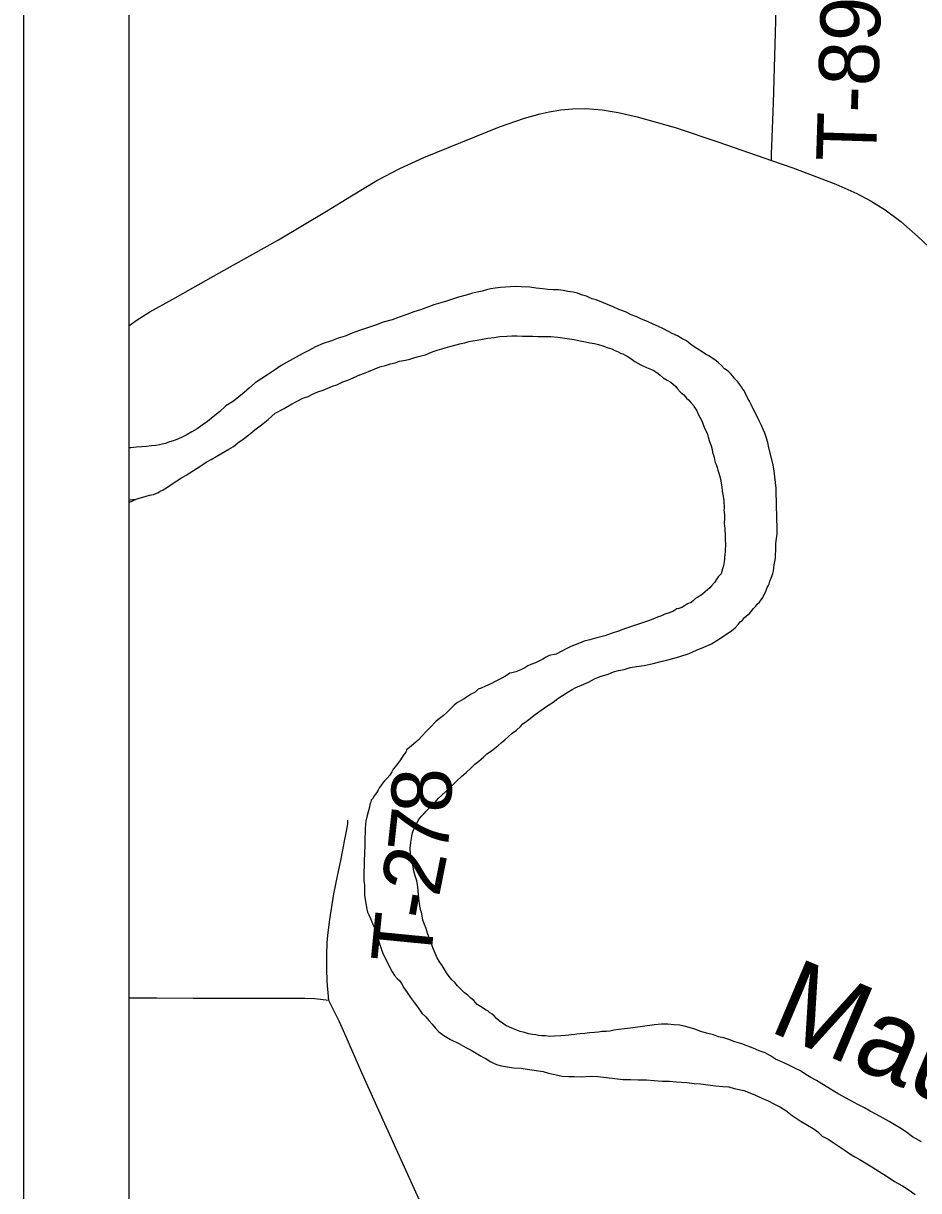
# Model space of a CAD drawing. Extents: x 0 to 64.8, y -5 to 22.
# Drawn here: x 2 to 2.849, y 18.186 to 19.293 of the extents above; entities that cross this region are included whole.
import ezdxf

# ---------------------------------------------------------------- set-up
doc = ezdxf.new("R2010")
doc.units = 0
for name, color, linetype in [('GM_X_Adjacent_County', 7, 'Continuous'), ('GM_X_County', 7, 'Continuous'), ('GM_X_Major_River', 7, 'Continuous'), ('GM_X_Major_River_Text', 7, 'Continuous'), ('GM_X_Minor_River', 7, 'Continuous'), ('GM_X_Township', 7, 'Continuous'), ('GM_X_Township_Road', 7, 'Continuous'), ('GM_X_Township_Road_Text', 7, 'Continuous'), ('SH_Data', 7, 'Continuous')]:
    doc.layers.add(name, color=color, linetype=linetype)

msp = doc.modelspace()

# ---------------------------------------------------------------- linework, layer by layer
at = {"layer": 'GM_X_Adjacent_County'}
msp.add_lwpolyline([(2.1, 19.9176), (2.1, 14.1), (8.9, 14.1), (8.9, 19.781)], dxfattribs=at)
at = {"layer": 'GM_X_County'}
msp.add_lwpolyline([(2.1, 19.9176), (2.1, 14.1), (8.9, 14.1), (8.9, 19.781)], dxfattribs=at)
at = {"layer": 'GM_X_Major_River'}
for points in [[(2.7137, 18.7927), (2.7137, 18.7957), (2.7138, 18.7999), (2.7143, 18.8044), (2.7148, 18.8086), (2.7149, 18.812), (2.715, 18.8162), (2.7147, 18.8223), (2.7145, 18.8272), (2.7142, 18.8337), (2.7144, 18.8402), (2.7141, 18.8463), (2.7139, 18.8523), (2.7132, 18.8577), (2.7126, 18.863), (2.712, 18.8687), (2.711, 18.8741), (2.7103, 18.8783), (2.7071, 18.8905), (2.7061, 18.8955), (2.7047, 18.8997), (2.7033, 18.9043), (2.7018, 18.9078), (2.7, 18.9116), (2.6982, 18.9154), (2.6967, 18.9189), (2.6949, 18.922), (2.6934, 18.9254), (2.6916, 18.9289), (2.6902, 18.9316), (2.6887, 18.9347), (2.6872, 18.9374), (2.6858, 18.9401), (2.6847, 18.9424), (2.684, 18.9443), (2.6825, 18.9462), (2.681, 18.9485), (2.6792, 18.9509), (2.6777, 18.9532), (2.6747, 18.9559), (2.6729, 18.9586), (2.6706, 18.9609), (2.6684, 18.9633), (2.665, 18.9656), (2.662, 18.9687), (2.6594, 18.9711), (2.6568, 18.9734), (2.6542, 18.975), (2.6508, 18.9774), (2.647, 18.9793), (2.6429, 18.9821), (2.6373, 18.9856), (2.6328, 18.9888), (2.629, 18.9919), (2.6245, 18.9943), (2.6204, 18.9967), (2.6155, 18.9991), (2.6106, 19.0015), (2.6064, 19.0038), (2.6023, 19.0058), (2.5974, 19.0079), (2.5921, 19.0103), (2.5864, 19.0127), (2.5819, 19.0147), (2.5766, 19.0167), (2.571, 19.0195), (2.5649, 19.0219), (2.5593, 19.0243), (2.5434, 19.0308), (2.5396, 19.032), (2.5366, 19.0332), (2.534, 19.0344), (2.5294, 19.0356), (2.5257, 19.0372), (2.5215, 19.0381), (2.5165, 19.039), (2.512, 19.0398), (2.5074, 19.0403), (2.5025, 19.0404), (2.4975, 19.0409), (2.4926, 19.0414), (2.4865, 19.0419), (2.4804, 19.0428), (2.4721, 19.0434), (2.4667, 19.0435), (2.4621, 19.0433), (2.4572, 19.043), (2.4526, 19.0427), (2.4476, 19.0421), (2.4434, 19.0414), (2.4392, 19.0404), (2.435, 19.0393), (2.4304, 19.0383), (2.425, 19.0369), (2.4201, 19.0355), (2.4128, 19.0334), (2.407, 19.0316), (2.4013, 19.0298), (2.3959, 19.028), (2.3894, 19.0263), (2.3828, 19.0238)], [(2.3828, 19.0238), (2.3767, 19.0216), (2.3702, 19.0195), (2.3636, 19.017), (2.3563, 19.0145), (2.3498, 19.012), (2.3414, 19.0099), (2.3341, 19.007), (2.3264, 19.0045), (2.3187, 19.0017), (2.3118, 18.9992), (2.3052, 18.9966), (2.2987, 18.9945), (2.2922, 18.992), (2.2845, 18.9895), (2.2772, 18.9863), (2.2706, 18.983), (2.2645, 18.9797), (2.2444, 18.9688), (2.2382, 18.9643), (2.2324, 18.9603), (2.2262, 18.9562), (2.22, 18.9522), (2.2146, 18.9474), (2.2095, 18.9429), (2.2045, 18.9389), (2.1994, 18.9348), (2.1921, 18.9304), (2.1859, 18.9248), (2.18, 18.92), (2.1746, 18.9156), (2.1696, 18.9119), (2.1649, 18.9086), (2.1599, 18.9057), (2.1545, 18.9027), (2.1499, 18.9002), (2.1456, 18.8984), (2.1422, 18.8973), (2.1387, 18.8963), (2.1349, 18.8948), (2.1318, 18.8941), (2.1291, 18.8934), (2.1257, 18.8928), (2.1215, 18.8925), (2.1169, 18.8918), (2.1123, 18.8915), (2.1074, 18.8913), (2.102, 18.8906), (2.1, 18.8905)], [(2.1, 18.8414), (2.102, 18.8412), (2.1039, 18.8415), (2.107, 18.8419), (2.1089, 18.8426), (2.112, 18.8433), (2.1154, 18.8443), (2.1197, 18.8457), (2.1235, 18.8464), (2.1258, 18.8471), (2.1277, 18.8478), (2.1296, 18.8493), (2.1327, 18.8508), (2.1366, 18.8533), (2.1412, 18.8563), (2.1455, 18.8592), (2.1501, 18.8622), (2.1544, 18.8647), (2.1683, 18.8735), (2.1733, 18.8768), (2.178, 18.8794), (2.1834, 18.8827), (2.1872, 18.8849), (2.1911, 18.8871), (2.195, 18.8893), (2.1992, 18.8918), (2.2035, 18.8952), (2.2085, 18.8989), (2.2139, 18.9029), (2.2194, 18.9077), (2.226, 18.9125), (2.2322, 18.9173), (2.2388, 18.9233), (2.2473, 18.928), (2.2538, 18.9317), (2.2596, 18.9349), (2.265, 18.9375), (2.27, 18.9393), (2.2743, 18.9415), (2.2793, 18.9436), (2.2843, 18.9454), (2.2889, 18.9472), (2.2931, 18.949), (2.2973, 18.9504), (2.3031, 18.953), (2.3077, 18.9548), (2.3127, 18.9569), (2.3177, 18.9591), (2.3227, 18.9609), (2.3273, 18.9631), (2.3327, 18.9652), (2.3381, 18.9674), (2.3435, 18.9688), (2.3481, 18.9702), (2.3527, 18.9712), (2.3569, 18.9727), (2.3623, 18.9737), (2.3665, 18.9747), (2.3703, 18.9758), (2.3734, 18.9768), (2.3772, 18.9779), (2.3814, 18.9789), (2.3849, 18.9804), (2.3887, 18.9818), (2.3926, 18.9832), (2.3968, 18.9843), (2.3999, 18.9854), (2.4045, 18.9868), (2.4152, 18.9896), (2.4186, 18.9903), (2.4225, 18.9913), (2.4263, 18.992), (2.4305, 18.9926), (2.4355, 18.9937), (2.4405, 18.9947), (2.4466, 18.9953), (2.4519, 18.996), (2.4584, 18.9966), (2.4634, 18.9968), (2.4683, 18.9967), (2.4733, 18.9966), (2.4779, 18.9965), (2.4832, 18.9964), (2.4881, 18.9963), (2.4939, 18.9961), (2.5003, 18.996), (2.5068, 18.9955), (2.5136, 18.9946)], [(2.5136, 18.9946), (2.5224, 18.9932), (2.5281, 18.9919), (2.533, 18.9911), (2.5372, 18.9902), (2.5417, 18.9894), (2.5455, 18.9885), (2.5497, 18.9873), (2.5538, 18.9857), (2.558, 18.9844), (2.561, 18.9828), (2.564, 18.9816), (2.5663, 18.9804), (2.5685, 18.9796), (2.5708, 18.9784), (2.5727, 18.9776), (2.5761, 18.9753), (2.5798, 18.9725), (2.5855, 18.9693), (2.5911, 18.9669), (2.5957, 18.9649), (2.599, 18.9633), (2.602, 18.961), (2.6039, 18.9594), (2.6069, 18.9571), (2.6107, 18.9547), (2.614, 18.9527), (2.6189, 18.9488), (2.6204, 18.9465), (2.6234, 18.9434), (2.6263, 18.9407), (2.6289, 18.9376), (2.6308, 18.936), (2.6327, 18.934), (2.6356, 18.9306), (2.6367, 18.9286), (2.6386, 18.9255), (2.64, 18.9225), (2.6419, 18.919), (2.6437, 18.9155), (2.6451, 18.9117), (2.6466, 18.9079), (2.6484, 18.9044), (2.6494, 18.9006), (2.6509, 18.8964), (2.6523, 18.8925), (2.6534, 18.8891), (2.6537, 18.886), (2.6544, 18.8837), (2.6551, 18.8818), (2.6554, 18.8792), (2.6561, 18.8765), (2.6572, 18.8746), (2.6579, 18.8719), (2.6586, 18.8692), (2.6597, 18.8665), (2.6604, 18.8635), (2.6611, 18.8604), (2.6618, 18.8573), (2.6625, 18.8531), (2.6628, 18.8493), (2.6635, 18.8467), (2.6638, 18.8444), (2.6641, 18.8425), (2.6645, 18.8402), (2.6644, 18.8379), (2.6647, 18.8356), (2.6647, 18.8333), (2.6643, 18.8314), (2.6646, 18.8295), (2.6649, 18.8268), (2.6649, 18.8246), (2.6647, 18.8185), (2.6651, 18.8166), (2.6654, 18.8139), (2.6653, 18.8116), (2.6657, 18.8093), (2.6656, 18.8074), (2.6656, 18.8048), (2.6655, 18.8029), (2.6658, 18.7998), (2.6658, 18.7976), (2.6657, 18.7945), (2.6656, 18.7919), (2.6652, 18.7892), (2.6651, 18.7865), (2.6651, 18.7846), (2.6647, 18.7828), (2.6642, 18.7801), (2.6638, 18.7778), (2.663, 18.7756), (2.6617, 18.771), (2.659, 18.7681), (2.6578, 18.7662), (2.6555, 18.7628), (2.6527, 18.7595), (2.6511, 18.7576), (2.6488, 18.7557), (2.6465, 18.7539), (2.6442, 18.7517), (2.6414, 18.7498)], [(2.3675, 18.5162), (2.368, 18.5199), (2.3684, 18.5226), (2.3692, 18.5252), (2.37, 18.5283), (2.3716, 18.5313), (2.3732, 18.5343), (2.3748, 18.5377), (2.3764, 18.5395), (2.378, 18.5414), (2.3799, 18.5432), (2.3819, 18.5459), (2.3842, 18.5481), (2.3866, 18.5503), (2.3885, 18.5526), (2.3905, 18.5544), (2.3936, 18.5581), (2.3967, 18.5607), (2.4006, 18.5644), (2.4111, 18.5745), (2.4154, 18.5789), (2.4201, 18.5826), (2.4243, 18.5867), (2.4282, 18.5904), (2.4321, 18.5934), (2.4364, 18.5971), (2.4395, 18.6004), (2.443, 18.6026), (2.4469, 18.6052), (2.4504, 18.6082), (2.4531, 18.6108), (2.4566, 18.6134), (2.4601, 18.6167), (2.4636, 18.6197), (2.4678, 18.6226), (2.4714, 18.6263), (2.4737, 18.6286), (2.4768, 18.6308), (2.4807, 18.6337), (2.4842, 18.6367), (2.4888, 18.64), (2.4966, 18.6455), (2.5024, 18.6492), (2.507, 18.6529), (2.5113, 18.6555), (2.5159, 18.6584), (2.5205, 18.6613), (2.524, 18.6631), (2.5294, 18.6653), (2.5359, 18.6682), (2.5417, 18.6715), (2.5471, 18.6736), (2.5548, 18.6758), (2.5598, 18.6779), (2.5644, 18.6793), (2.5698, 18.6804), (2.5755, 18.6821), (2.5816, 18.6831), (2.5889, 18.6841), (2.5973, 18.6858), (2.6046, 18.6879), (2.6111, 18.6893), (2.6172, 18.6911), (2.6226, 18.6925), (2.6314, 18.6953), (2.6384, 18.6986), (2.6453, 18.7014), (2.6526, 18.7047), (2.6588, 18.7084), (2.6716, 18.7168), (2.6751, 18.7198), (2.6778, 18.7228), (2.6798, 18.7254), (2.6821, 18.7272), (2.684, 18.7295), (2.686, 18.7313), (2.6883, 18.7332), (2.6903, 18.7354), (2.6926, 18.738), (2.6946, 18.7402), (2.6961, 18.7421), (2.6981, 18.744), (2.6997, 18.7462), (2.7012, 18.7485), (2.7024, 18.7507), (2.704, 18.7537), (2.7048, 18.756), (2.7056, 18.7579), (2.7065, 18.7597), (2.7073, 18.7616), (2.7081, 18.7639), (2.7089, 18.7662), (2.7101, 18.7695), (2.7109, 18.7714), (2.7113, 18.7737), (2.7118, 18.7764), (2.7122, 18.7794), (2.7127, 18.7828), (2.7132, 18.7862), (2.7132, 18.7896), (2.7137, 18.7927)], [(2.6414, 18.7498), (2.6395, 18.7487), (2.6376, 18.7476), (2.6356, 18.7458), (2.6333, 18.7439), (2.6298, 18.7425), (2.6271, 18.7406), (2.6244, 18.7392), (2.6217, 18.7381), (2.6198, 18.7378), (2.616, 18.7352), (2.6114, 18.7338), (2.6083, 18.7327), (2.6052, 18.7313), (2.6014, 18.7298), (2.5971, 18.728), (2.5921, 18.7262), (2.5864, 18.7241), (2.5749, 18.7205), (2.571, 18.7191), (2.5645, 18.7166), (2.5583, 18.7148), (2.5514, 18.7123), (2.5438, 18.7102), (2.5372, 18.7085), (2.5319, 18.7071), (2.5276, 18.7053), (2.5234, 18.7038), (2.5192, 18.702), (2.5149, 18.6999), (2.5107, 18.6977), (2.5053, 18.6948), (2.4988, 18.6934), (2.4957, 18.6919), (2.4926, 18.6901), (2.4895, 18.6886), (2.4857, 18.6865), (2.4814, 18.685), (2.4784, 18.6836), (2.4757, 18.6817), (2.4718, 18.6799), (2.4672, 18.6781), (2.4634, 18.6771), (2.4614, 18.6767), (2.4572, 18.6738), (2.4533, 18.6716), (2.4487, 18.6694), (2.4433, 18.6665), (2.4383, 18.6643), (2.4341, 18.6625), (2.4314, 18.6615), (2.4286, 18.6589), (2.4248, 18.6567), (2.4213, 18.6545), (2.4182, 18.6523), (2.4147, 18.6504), (2.4124, 18.6493), (2.4105, 18.6479), (2.4086, 18.6464), (2.4043, 18.6419), (2.4012, 18.6393), (2.3984, 18.6367), (2.3945, 18.6334), (2.3914, 18.6312), (2.3856, 18.6249), (2.3817, 18.6212), (2.3782, 18.6174), (2.3743, 18.6133), (2.37, 18.6093), (2.3661, 18.6063), (2.3638, 18.6044), (2.3626, 18.6018), (2.3602, 18.5988), (2.3578, 18.5947), (2.3551, 18.591), (2.3527, 18.588), (2.3508, 18.5857), (2.3496, 18.5831), (2.3476, 18.5801), (2.3449, 18.5771), (2.3425, 18.5745), (2.3409, 18.5727), (2.3398, 18.5708), (2.3378, 18.5682), (2.3366, 18.5659), (2.335, 18.5633), (2.3331, 18.5607), (2.3315, 18.558), (2.3299, 18.5562), (2.3295, 18.5543), (2.3287, 18.5524), (2.3282, 18.5497), (2.3274, 18.5463), (2.3262, 18.5418), (2.3249, 18.5365), (2.3244, 18.5331), (2.3243, 18.5293), (2.3242, 18.5251), (2.3238, 18.521), (2.324, 18.5164), (2.3239, 18.5118)], [(2.7322, 18.3018), (2.7266, 18.3046), (2.7206, 18.3074), (2.7134, 18.3106), (2.7085, 18.3137), (2.7036, 18.3165), (2.698, 18.3185), (2.6923, 18.3209), (2.687, 18.3229), (2.6813, 18.325), (2.6749, 18.327), (2.6692, 18.3291), (2.6643, 18.3307), (2.6594, 18.3319), (2.6545, 18.3336), (2.648, 18.3352), (2.6424, 18.3369), (2.6367, 18.3389), (2.6314, 18.3406), (2.6268, 18.3418), (2.6227, 18.3427), (2.6173, 18.3432), (2.6113, 18.3437), (2.6052, 18.3438), (2.5987, 18.3432), (2.5757, 18.3399), (2.57, 18.3393), (2.5647, 18.3387), (2.5601, 18.338), (2.5562, 18.3373), (2.5528, 18.337), (2.549, 18.3367), (2.5455, 18.3361), (2.5417, 18.3358), (2.5371, 18.3355), (2.5326, 18.3348), (2.528, 18.3346), (2.5249, 18.3342), (2.523, 18.3339), (2.5196, 18.3336), (2.5173, 18.3333), (2.5142, 18.333), (2.5096, 18.3327), (2.5039, 18.3324), (2.4993, 18.3322), (2.4952, 18.3326), (2.4917, 18.3327), (2.4887, 18.3332), (2.486, 18.3336), (2.483, 18.3341), (2.4792, 18.3345), (2.4754, 18.3358), (2.4713, 18.337), (2.4679, 18.3382), (2.4648, 18.3394), (2.4611, 18.341), (2.4577, 18.3426), (2.4543, 18.3446), (2.4513, 18.347), (2.4487, 18.3493), (2.4464, 18.3516), (2.4446, 18.3532), (2.4423, 18.3544), (2.4404, 18.3563), (2.4382, 18.3575), (2.4352, 18.3595), (2.4303, 18.3626), (2.4273, 18.3661), (2.4243, 18.3685), (2.4214, 18.3712), (2.4184, 18.3736), (2.4116, 18.3802), (2.4091, 18.3833), (2.4064, 18.386), (2.4038, 18.3891), (2.4013, 18.3926), (2.3991, 18.3964), (2.3972, 18.3995), (2.3946, 18.403), (2.3924, 18.4068), (2.3906, 18.4111), (2.3888, 18.4157), (2.3867, 18.4207), (2.3849, 18.4256), (2.3834, 18.4302), (2.382, 18.4345), (2.3806, 18.4383), (2.3788, 18.4425), (2.3778, 18.4486), (2.3764, 18.454), (2.3754, 18.4605), (2.3748, 18.4669), (2.3742, 18.4742), (2.3731, 18.4799), (2.3717, 18.4845), (2.3703, 18.4891), (2.3693, 18.4948), (2.3683, 18.4998), (2.3672, 18.5051), (2.367, 18.5108), (2.3675, 18.5162)], [(2.3239, 18.5118), (2.3235, 18.5077), (2.3234, 18.5042), (2.3233, 18.5004), (2.3232, 18.4974), (2.3232, 18.494), (2.323, 18.4887), (2.3229, 18.4849), (2.3229, 18.4814), (2.3228, 18.4795), (2.3232, 18.4776), (2.3235, 18.4757), (2.3234, 18.4715), (2.3237, 18.4662), (2.3253, 18.4544), (2.3264, 18.4502), (2.3278, 18.4475), (2.3293, 18.444), (2.3311, 18.4394), (2.3332, 18.4344), (2.335, 18.4294), (2.3364, 18.4245), (2.3379, 18.4199), (2.3393, 18.4157), (2.3407, 18.4118), (2.3429, 18.4072), (2.3451, 18.403), (2.3476, 18.3976), (2.3498, 18.3934), (2.352, 18.3899), (2.3546, 18.3872), (2.3569, 18.3852), (2.3587, 18.3825), (2.3609, 18.3783), (2.3639, 18.3737), (2.3672, 18.369), (2.3709, 18.364), (2.3746, 18.3593), (2.3779, 18.3543), (2.3816, 18.3508), (2.3846, 18.3473), (2.3876, 18.3438), (2.3905, 18.3404), (2.3939, 18.3365), (2.3988, 18.3329), (2.4052, 18.3294), (2.4131, 18.3254), (2.4195, 18.3218), (2.4247, 18.319), (2.4293, 18.3163), (2.4341, 18.3135), (2.4364, 18.3123), (2.4387, 18.3111), (2.4428, 18.3084), (2.4454, 18.3072), (2.4488, 18.3056), (2.4534, 18.3043), (2.4591, 18.3034), (2.4648, 18.3025), (2.472, 18.302), (2.4777, 18.3011), (2.4929, 18.2989), (2.4982, 18.2972), (2.5042, 18.2959), (2.5111, 18.2946), (2.5172, 18.2941), (2.5225, 18.294), (2.529, 18.2939), (2.5377, 18.2944), (2.545, 18.2942), (2.553, 18.2933), (2.5609, 18.2924), (2.5685, 18.2914), (2.5758, 18.2913), (2.583, 18.2911), (2.591, 18.2909), (2.5982, 18.2904), (2.6058, 18.2898), (2.6127, 18.2897), (2.6195, 18.2891), (2.6291, 18.2885), (2.6363, 18.2876), (2.6424, 18.2871), (2.6492, 18.2862), (2.6568, 18.2852), (2.6633, 18.2847), (2.669, 18.2842), (2.6743, 18.2829), (2.6788, 18.2817), (2.6834, 18.2808), (2.6875, 18.2792), (2.6943, 18.2764), (2.7004, 18.2736), (2.7064, 18.2712), (2.7124, 18.268), (2.7181, 18.2652), (2.7233, 18.262), (2.7293, 18.2573), (2.7368, 18.2522), (2.7436, 18.2479), (2.7492, 18.2447)], [(2.8518, 18.2321), (2.8432, 18.2369), (2.8368, 18.242), (2.8312, 18.2455), (2.8259, 18.2487), (2.821, 18.2514), (2.8154, 18.2546), (2.809, 18.2582), (2.803, 18.2614), (2.7977, 18.2645), (2.7928, 18.2669), (2.7868, 18.2701), (2.7804, 18.2737), (2.7729, 18.2776), (2.768, 18.2804), (2.7631, 18.2836), (2.7574, 18.2871), (2.7522, 18.2903), (2.7469, 18.2931), (2.742, 18.2962), (2.7371, 18.2994), (2.7322, 18.3018)], [(2.7492, 18.2447), (2.7534, 18.2416), (2.7575, 18.2377), (2.7639, 18.2345), (2.768, 18.2314), (2.7718, 18.229), (2.7755, 18.2266), (2.7793, 18.2239), (2.7838, 18.2207), (2.7886, 18.218), (2.7928, 18.2156), (2.8048, 18.2085), (2.8116, 18.2041), (2.8183, 18.1998), (2.8262, 18.1947), (2.8338, 18.1903), (2.8401, 18.1864), (2.8458, 18.1821)]]:
    msp.add_lwpolyline(points, dxfattribs=at)
at = {"layer": 'GM_X_Minor_River'}
msp.add_lwpolyline([(2.1, 18.8386), (2.1069, 18.8418)], dxfattribs=at)
at = {"layer": 'GM_X_Township'}
msp.add_lwpolyline([(2.1, 19.9176), (2.1, 14.1), (5.5757, 14.1)], dxfattribs=at)
at = {"layer": 'GM_X_Township_Road'}
for points in [[(2.7094, 19.1632), (2.7097, 19.1695), (2.7099, 19.1769), (2.7114, 19.2174), (2.7157, 19.3627)], [(2.1, 19.0063), (2.1069, 19.0114), (2.1201, 19.0196), (2.1418, 19.0316), (2.1607, 19.0424), (2.1904, 19.0592), (2.242, 19.088), (2.2874, 19.115), (2.3112, 19.1295), (2.3351, 19.144), (2.3571, 19.1556), (2.3797, 19.166), (2.4517, 19.1951), (2.4752, 19.2033), (2.4902, 19.2074), (2.4988, 19.2094), (2.5097, 19.2112), (2.5209, 19.2121), (2.5333, 19.2123), (2.5488, 19.2112), (2.5642, 19.2088), (2.5823, 19.2046), (2.6182, 19.1943), (2.6595, 19.1806), (2.7094, 19.1632)], [(2.7094, 19.1632), (2.7299, 19.1561), (2.7706, 19.1406), (2.7905, 19.1318), (2.8042, 19.1246), (2.8174, 19.1164), (2.8323, 19.1051), (2.8486, 19.0908), (2.894, 19.0482), (2.9025, 19.0392), (2.9102, 19.0294), (2.9183, 19.0162), (2.9391, 18.978), (2.9457, 18.9639), (2.9498, 18.9522), (2.9537, 18.9372), (2.9566, 18.9219), (2.9583, 18.9065), (2.9586, 18.894), (2.9582, 18.8754), (2.9584, 18.8723), (2.959, 18.8693), (2.9601, 18.8664), (2.9609, 18.8652)], [(2.2898, 18.3661), (2.2883, 18.3843), (2.2877, 18.3967), (2.2877, 18.4091), (2.2883, 18.4215), (2.2891, 18.4307), (2.2906, 18.443), (2.2946, 18.4675), (2.2984, 18.4858), (2.2998, 18.493), (2.3014, 18.5005), (2.3026, 18.5072), (2.3047, 18.5174), (2.3065, 18.5269), (2.3078, 18.5337), (2.3079, 18.5373)], [(2.1265, 18.3684), (2.1, 18.3685)], [(2.2898, 18.3661), (2.2842, 18.3669), (2.2765, 18.3677), (2.2671, 18.3681), (2.2297, 18.3682), (2.161, 18.3683), (2.1265, 18.3684)], [(2.4693, 17.9691), (2.4654, 17.9778), (2.4552, 18.0004), (2.4476, 18.0175), (2.4373, 18.0401), (2.4232, 18.0712), (2.4146, 18.0911), (2.4121, 18.0967), (2.4031, 18.1163), (2.3878, 18.1503), (2.3428, 18.2494), (2.321, 18.2975), (2.3061, 18.3317), (2.2997, 18.3459), (2.2898, 18.3661)]]:
    msp.add_lwpolyline(points, dxfattribs=at)
at = {"layer": 'SH_Data'}
for p, q in [((2, 21), (2, 14)), ((2.1, 20.9), (2.1, 14.1))]:
    msp.add_line(p, q, dxfattribs=at)

# ---------------------------------------------------------------- texts
at = {"layer": 'GM_X_Major_River_Text'}
msp.add_text('Maumee', height=0.0758, rotation=337.0508, dxfattribs=at).set_placement((2.7053, 18.3378))
at = {"layer": 'GM_X_Township_Road_Text'}
for s, height, rotation, p in [('T-89', 0.05682, 88.2318, (2.8086, 19.1614)), ('8', 0.0568, 89.5581, (2.4059, 18.5443)), ('7', 0.0568, 83.7519, (2.4017, 18.5032)), ('2', 0.0568, 78.6658, (2.394, 18.4634)), ('-', 0.0568, 80.1212, (2.3901, 18.4408)), ('T', 0.0568, 84.4295, (2.3861, 18.3997))]:
    msp.add_text(s, height=height, rotation=rotation, dxfattribs=at).set_placement(p)

doc.saveas('drawing.dxf')
